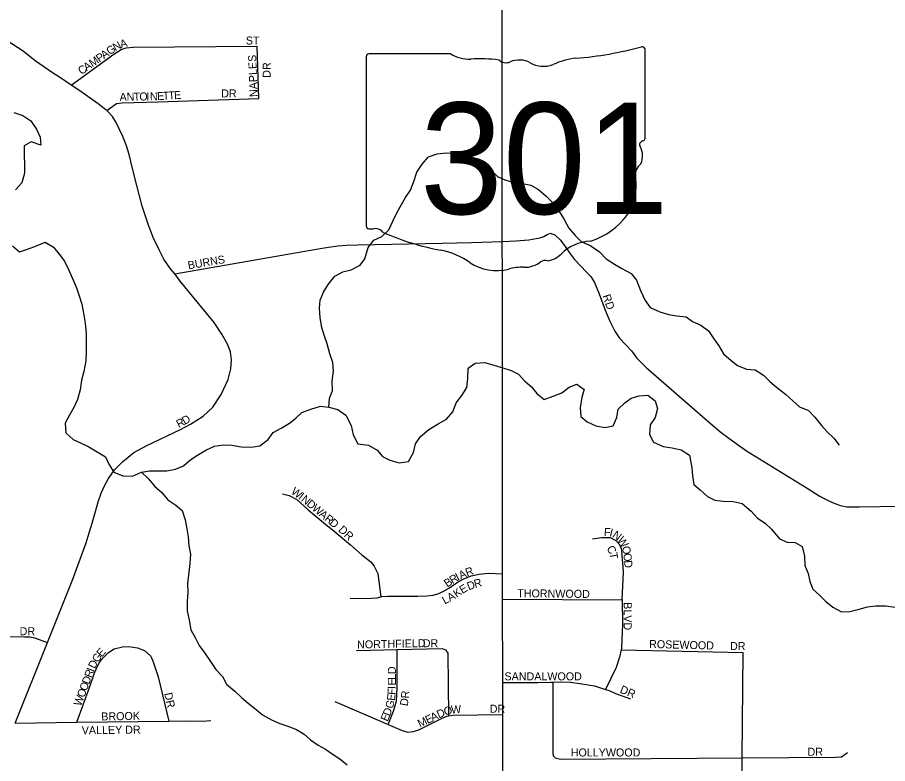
# Model space of a CAD drawing. Extents: x 1857828 to 2277390, y 930619 to 1324581.
# Drawn here: x 2081484 to 2086916, y 1239081 to 1243739 of the extents above; entities that cross this region are included whole.
import ezdxf

# ---------------------------------------------------------------- set-up
doc = ezdxf.new("R2010")
doc.units = 0
for name, color, linetype in [('GM_X_City_Street', 7, 'Continuous'), ('GM_X_City_Street_Text', 7, 'Continuous'), ('GM_X_Minor_River', 7, 'Continuous'), ('GM_X_State_Location', 7, 'Continuous'), ('GM_X_State_Route', 7, 'Continuous'), ('GM_X_State_Shield', 7, 'Continuous')]:
    doc.layers.add(name, color=color, linetype=linetype)

msp = doc.modelspace()

# ---------------------------------------------------------------- linework, layer by layer
at = {"layer": 'GM_X_City_Street'}
for points in [[(2081470.6, 1239334.1), (2081671.9, 1239837.7), (2081829.2, 1240231.2), (2081884.8, 1240380.1), (2081912.6, 1240458.5), (2081932.4, 1240520.8), (2081950.2, 1240581.1), (2081972, 1240655.5), (2081987.7, 1240713.8), (2082005.6, 1240768.1), (2082027.5, 1240814.4), (2082051.4, 1240860.7), (2082089.3, 1240915), (2082139.3, 1240965.5), (2082211.4, 1241022), (2082291.6, 1241066.6), (2082502.1, 1241166), (2082564.2, 1241200.4), (2082642.4, 1241248.9), (2082704.4, 1241305.4), (2082756.3, 1241384), (2082800.1, 1241478.6), (2082815.8, 1241544.9), (2082819.6, 1241601.1), (2082813.4, 1241651.3), (2082795, 1241699.4), (2082760.6, 1241761.4), (2082712, 1241833.4), (2082606.9, 1241963.5), (2082499.8, 1242091.4), (2082467.5, 1242137.4), (2082439.2, 1242169.4), (2082398.7, 1242229.5), (2082368.3, 1242287.5), (2082331.8, 1242365.7), (2082299.3, 1242447.8), (2082262.6, 1242560.1), (2082229.8, 1242690.4), (2082201.2, 1242794.7), (2082180.7, 1242882.9), (2082164.4, 1242937), (2082142, 1242995.2), (2082119.7, 1243043.2), (2082099.4, 1243083.3), (2082077.1, 1243119.3), (2082041.2, 1243156.6), (2082036.7, 1243161.3), (2081988.4, 1243199.2), (2081873.4, 1243280.9), (2081819.5, 1243316.5), (2081752.5, 1243360.7), (2081702.1, 1243392.6), (2081595.2, 1243468.3), (2081518.6, 1243528.2), (2081413.8, 1243596)], [(2081819.5, 1243316.5), (2082085.3, 1243508.2), (2082109.4, 1243524.2), (2082131.5, 1243538.2), (2082163.6, 1243548.2), (2082205.8, 1243552.2), (2082980.5, 1243559.4)], [(2082990.2, 1243232.6), (2082980.5, 1243559.4)], [(2082041.2, 1243156.6), (2082103, 1243201.5), (2082137.1, 1243205.4), (2082362, 1243211.2), (2082990.2, 1243232.6)], [(2084511, 1242340.9), (2084594.6, 1242344.3), (2084676.9, 1242350.7), (2084745.2, 1242363.1), (2084769.3, 1242371.3), (2084791.3, 1242383.4), (2084811.3, 1242391.5), (2084820.2, 1242388.4)], [(2084820.2, 1242388.4), (2084820.7, 1242388.2), (2084839.5, 1242381.6), (2084871.8, 1242349.7), (2084900.1, 1242315.7), (2084930.5, 1242269.7), (2084960.8, 1242227.6), (2085003.2, 1242183.7), (2085033.5, 1242151.7), (2085063.8, 1242121.7), (2085086.1, 1242083.7), (2085116.5, 1242013.6), (2085153.2, 1241911.4), (2085181.6, 1241843.2), (2085214, 1241781.1), (2085242.4, 1241737.1), (2085282.8, 1241695.1), (2085317.1, 1241657.2), (2085351.5, 1241611.2), (2085414, 1241549.2), (2085422, 1241542.3), (2085423.5, 1241541.1)], [(2082467.5, 1242137.4), (2083312.8, 1242286), (2083399.1, 1242300.5), (2083441.3, 1242306.7), (2083483.5, 1242312.9), (2083535.7, 1242317.2), (2083610, 1242319.6), (2084136.4, 1242330.1), (2084319.3, 1242333), (2084511, 1242340.9)], [(2085423.5, 1241541.1), (2085809.5, 1241205.8), (2085878.1, 1241147.9), (2085916.4, 1241118), (2085970.8, 1241078.1), (2086035.3, 1241034.2), (2086414.2, 1240799.1), (2086488.7, 1240753.3), (2086517, 1240737.4), (2086553.2, 1240719.5), (2086587.4, 1240703.6), (2086621.6, 1240691.7), (2086661.9, 1240683.9), (2086738.2, 1240684.3), (2086996.2, 1240686.9)], [(2083139.7, 1240764.4), (2083180, 1240755), (2083228.5, 1240729.6), (2083299.7, 1240664.5), (2083397.2, 1240583.7), (2083462.2, 1240532.5), (2083563.9, 1240445.7), (2083635, 1240384.6), (2083689.9, 1240339.3), (2083710.4, 1240313.6), (2083733.1, 1240267.8), (2083753.2, 1240122.1)], [(2085259.1, 1240103.2), (2085266.6, 1240275.7), (2085263.7, 1240335.8), (2085259.1, 1240375.9), (2085256.5, 1240415.9), (2085244, 1240445.8), (2085221.6, 1240471.6), (2085187.1, 1240491.1), (2085132.9, 1240490.3), (2085074.9, 1240481.5)], [(2083560.7, 1240112.9), (2083659.1, 1240112.3), (2083729.3, 1240115.3), (2083753.2, 1240122.1), (2083759.3, 1240123.8), (2083793.4, 1240126.3), (2083984.1, 1240125), (2084040.3, 1240127.8), (2084080.3, 1240132.4), (2084114.3, 1240142.9), (2084148.2, 1240159.5), (2084182.1, 1240178), (2084231.7, 1240212.8), (2084267.6, 1240231.3), (2084317.5, 1240252.1), (2084367.5, 1240262.8), (2084423.6, 1240269.7), (2084512.7, 1240264.8)], [(2084512.8, 1240106.5), (2085259.1, 1240103.2), (2085261.4, 1239946.9), (2085256.6, 1239858.6), (2085255.5, 1239800.4), (2085253.2, 1239791.1), (2085242.3, 1239746.1), (2085221.1, 1239679.7), (2085155.9, 1239543.4)], [(2080187.9, 1239829.9), (2081047.7, 1239830.3), (2081089.8, 1239832.9), (2081113.8, 1239835.2), (2081145.8, 1239843.7), (2081182.9, 1239855.4), (2081209.8, 1239864.7), (2081231.8, 1239871), (2081267.9, 1239873.5), (2081332.1, 1239874.5), (2081530.8, 1239871.3), (2081563, 1239871.8), (2081591.1, 1239866.2), (2081671.9, 1239837.7)], [(2081853.8, 1239338.6), (2081932.9, 1239556.3), (2081963.8, 1239641), (2081981.2, 1239685.3), (2081996.9, 1239711.6), (2082012.6, 1239733.9), (2082052.2, 1239774.6), (2082088, 1239797.1), (2082140, 1239809.9), (2082180.1, 1239812.4), (2082234.4, 1239803.2), (2082276.8, 1239787.8), (2082317.5, 1239752.3), (2082332.1, 1239716.4), (2082361.6, 1239622.6), (2082429.9, 1239345.3)], [(2083599.7, 1239786.7), (2083854.5, 1239792.3), (2084135.4, 1239798.4), (2084155.6, 1239790.7), (2084170, 1239770.8), (2084174.3, 1239378.9)], [(2083798, 1239325.9), (2083832.1, 1239407.1), (2083839.7, 1239435.3), (2083851.1, 1239473.6), (2083854, 1239553.8), (2083854.5, 1239792.3)], [(2085253.2, 1239791.1), (2086014.6, 1239775.3)], [(2086020.9, 1236475.6), (2086016, 1236628.4), (2086013.5, 1236704), (2086013.7, 1236969.4), (2086013.9, 1237280.7), (2086014, 1237359.6), (2086012.5, 1237660.7), (2086008.5, 1238482.2), (2086007, 1238790.9), (2086009.5, 1239117.7), (2086014.6, 1239775.3)], [(2084513.3, 1239587.2), (2084732.7, 1239586.5), (2084813, 1239589.6), (2084827, 1239589.8), (2084875.2, 1239590.5), (2084935.4, 1239589.4), (2084995.8, 1239580.2), (2085086.3, 1239565.5), (2085155.9, 1239543.4), (2085177.1, 1239536.7), (2085217.5, 1239519.2), (2085312.3, 1239484.5)], [(2084827, 1239589.8), (2084825.6, 1239142.7), (2084829.8, 1239126.8), (2084842, 1239116.9), (2084874.2, 1239109.4), (2086009.5, 1239117.7), (2086590.3, 1239122), (2086628.4, 1239122.5), (2086666.1, 1239149.1)], [(2083465.8, 1239468.1), (2083778.9, 1239334.2), (2083798, 1239325.9), (2083886, 1239287.6), (2083920.3, 1239276.1), (2083956.4, 1239280.6), (2083994.3, 1239293.2), (2084135.8, 1239365.4), (2084165.7, 1239377.9), (2084174.3, 1239378.9), (2084201.8, 1239382.4), (2084513.4, 1239386.8)], [(2081470.6, 1239334.1), (2081853.8, 1239338.6), (2082429.9, 1239345.3), (2082564.3, 1239346.9), (2082640.6, 1239345.9), (2082690.7, 1239350.7)]]:
    msp.add_lwpolyline(points, dxfattribs=at)
at = {"layer": 'GM_X_Minor_River'}
for points in [[(2081462.4, 1243144.9), (2081516.8, 1243127.4), (2081567.5, 1243093.8), (2081602.3, 1243042), (2081624.9, 1242992), (2081629.6, 1242941.8), (2081569.1, 1242961.2), (2081525.2, 1242936.6), (2081525.9, 1242878.3), (2081528.6, 1242816), (2081527.2, 1242765.8), (2081511.9, 1242705.3), (2081472.2, 1242662.6)], [(2083427.4, 1241305.6), (2083432.7, 1241360), (2083450.2, 1241410.4), (2083449.5, 1241468.7), (2083456.8, 1241531.1), (2083452.1, 1241585.3), (2083433.4, 1241639.3), (2083418.6, 1241701.5), (2083401.9, 1241749.5), (2083385.2, 1241803.6), (2083374.4, 1241863.8), (2083369.7, 1241924.1), (2083373.1, 1241974.3), (2083394.6, 1242022.8), (2083424.2, 1242071.4), (2083465.7, 1242124.1), (2083515.6, 1242150.8), (2083567.7, 1242163.4), (2083623.6, 1242192.2), (2083653.3, 1242232.7), (2083674.5, 1242303.3), (2083708.2, 1242347.9), (2083758.1, 1242370.6), (2083801.8, 1242413.3), (2083827.3, 1242467.8), (2083854.7, 1242522.4), (2083882.3, 1242570.9), (2083905.8, 1242615.4), (2083937.5, 1242660), (2083958.9, 1242714.5), (2083978.3, 1242773), (2084009.8, 1242823.6), (2084049.5, 1242868.3), (2084103.5, 1242887), (2084159.7, 1242893.6), (2084220, 1242888.3), (2084280.4, 1242880.9), (2084334.9, 1242861.4), (2084387.5, 1242829.8), (2084438.2, 1242790.2), (2084480.9, 1242746.4), (2084527.4, 1242724.9), (2084575.8, 1242709.3), (2084636.1, 1242701.9), (2084688.5, 1242692.5), (2084737, 1242664.9), (2084785.8, 1242623.2), (2084832.5, 1242575.5), (2084863.2, 1242531.6), (2084898, 1242477.8), (2084926.8, 1242423.8), (2084965.5, 1242378), (2085004.1, 1242340.2), (2085062.7, 1242312.8), (2085117.4, 1242275.2), (2085160.1, 1242231.4), (2085210.8, 1242197.8), (2085257.3, 1242172.2), (2085315.9, 1242140.7), (2085348.6, 1242098.9), (2085373.5, 1242034.8), (2085402.4, 1241970.8), (2085435, 1241927), (2085493.6, 1241901.5), (2085550.1, 1241884.1), (2085600.4, 1241876.6), (2085658.7, 1241869.2), (2085699.3, 1241839.5), (2085749.8, 1241817.9), (2085798.4, 1241782.3), (2085831.2, 1241732.4), (2085863.8, 1241688.6), (2085892.6, 1241638.6), (2085939.3, 1241596.9), (2085979.8, 1241565.2), (2086036.4, 1241543.8), (2086088.7, 1241538.3), (2086141.3, 1241504.7), (2086181.9, 1241467), (2086222.6, 1241431.3), (2086279.3, 1241387.7), (2086324, 1241346), (2086366.7, 1241308.3), (2086423.2, 1241284.8), (2086461.9, 1241243), (2086504.7, 1241191.2), (2086539.3, 1241151.4), (2086580, 1241111.7), (2086614.7, 1241067.8)], [(2081452.3, 1242312.7), (2081497, 1242275), (2081547, 1242291.6), (2081603, 1242312.4), (2081657, 1242335.1), (2081709.6, 1242303.5), (2081744.3, 1242261.7), (2081776.9, 1242217.8), (2081801.7, 1242165.8), (2081828.5, 1242107.9), (2081853.3, 1242049.8), (2081870, 1241999.8), (2081886.7, 1241947.7), (2081895.4, 1241891.5), (2081906.2, 1241829.3), (2081913, 1241765.1), (2081913.7, 1241704.8), (2081912.4, 1241648.5), (2081911, 1241594.2), (2081897.7, 1241527.8), (2081884.3, 1241473.3), (2081875, 1241414.9), (2081859.6, 1241354.5), (2081836.1, 1241304), (2081810.6, 1241259.5), (2081781.1, 1241204.9), (2081785.8, 1241144.6), (2081832.5, 1241104.9), (2081881, 1241081.4), (2081929.5, 1241057.8), (2081982.1, 1241026.2), (2082032.7, 1240996.6), (2082055.4, 1240950.7), (2082086.1, 1240900.8), (2082142.7, 1240877.3), (2082202.9, 1240875.9), (2082258.9, 1240900.7), (2082309, 1240909.3), (2082363.3, 1240907.9), (2082417.5, 1240908.5), (2082471.7, 1240919.1), (2082521.6, 1240939.8), (2082567.4, 1240978.5), (2082615.2, 1241011.2), (2082665.1, 1241039.9), (2082715, 1241062.5), (2082769.2, 1241071.2), (2082821.5, 1241067.7), (2082879.8, 1241058.3), (2082942.1, 1241057), (2082996.3, 1241063.7), (2083050.1, 1241104.4), (2083079.7, 1241147), (2083129.6, 1241173.7), (2083181.4, 1241206.4), (2083221.3, 1241237), (2083259, 1241271.6), (2083315, 1241294.3), (2083375.1, 1241311.1), (2083427.4, 1241305.6), (2083483.8, 1241290.2), (2083534.4, 1241256.6), (2083567.4, 1241190.6), (2083580.1, 1241132.5), (2083608.9, 1241076.5), (2083675.3, 1241069.2), (2083730, 1241037.7), (2083762.6, 1240997.8), (2083809.1, 1240974.2), (2083867.5, 1240958.8), (2083925.7, 1240967.5), (2083957.2, 1241022.1), (2083968.6, 1241076.5), (2084000.2, 1241123.1), (2084051.9, 1241165.9), (2084109.7, 1241202.7)], [(2084109.7, 1241202.7), (2084161.6, 1241231.4), (2084201.2, 1241276.1), (2084222.7, 1241332.6), (2084258.3, 1241379.2), (2084289.8, 1241427.8), (2084295.2, 1241484.1), (2084298.4, 1241548.5), (2084342.2, 1241581.1), (2084402.5, 1241583.8), (2084458.9, 1241568.4), (2084513.4, 1241550.9), (2084565.8, 1241535.4), (2084612.3, 1241511.8), (2084651, 1241468), (2084693.6, 1241432.3), (2084726.2, 1241390.5), (2084772.9, 1241352.8), (2084828.9, 1241373.5), (2084882.9, 1241396.2), (2084928.7, 1241430.9), (2084976.7, 1241449.5), (2085021.3, 1241415.9), (2085007.8, 1241367.5), (2084996.6, 1241301), (2085001.2, 1241246.8), (2085041.8, 1241215.1), (2085094.3, 1241189.6), (2085150.7, 1241178.1), (2085202.8, 1241188.8), (2085226.3, 1241241.3), (2085233.7, 1241293.6), (2085275.4, 1241332.3), (2085315.3, 1241362.9), (2085365.3, 1241375.5), (2085419.5, 1241380.1), (2085466.2, 1241344.4), (2085480.8, 1241296.4), (2085465.4, 1241241.9), (2085433.8, 1241195.4), (2085430.5, 1241135), (2085455.2, 1241087.1), (2085515.8, 1241059.6), (2085572.1, 1241052.2), (2085628.6, 1241038.7), (2085679.2, 1241005.1), (2085694.2, 1240926.9), (2085698.8, 1240876.7), (2085707.5, 1240822.6), (2085746.1, 1240788.8), (2085792.8, 1240749.1), (2085837.3, 1240725.5), (2085889.6, 1240718.1), (2085951.9, 1240716.7), (2086008.3, 1240705.3), (2086065.1, 1240655.7), (2086103.8, 1240613.9), (2086152.4, 1240582.3), (2086191, 1240544.5), (2086242, 1240484.8), (2086288.4, 1240463.2), (2086338.7, 1240461.8), (2086383.2, 1240436.1), (2086398, 1240376), (2086400.7, 1240317.8), (2086421.4, 1240267.7), (2086430, 1240217.6), (2086450.7, 1240169.6), (2086491.3, 1240131.8), (2086530, 1240092.1), (2086574.6, 1240056.4), (2086629.2, 1240028.9), (2086681.4, 1240029.4), (2086739.5, 1240044.1), (2086791.6, 1240058.8), (2086843.7, 1240065.4), (2086904, 1240066.1), (2086964.4, 1240056.7)], [(2082258.9, 1240900.7), (2082301.6, 1240858.9), (2082342.4, 1240811.1), (2082383, 1240775.4), (2082423.7, 1240727.6), (2082472.4, 1240694), (2082512.9, 1240660.3), (2082531.7, 1240602.2), (2082542.4, 1240546.1), (2082549.1, 1240495.9), (2082553.8, 1240439.7), (2082564.4, 1240387.5), (2082561.1, 1240329.2), (2082552, 1240256.7), (2082544.6, 1240204.4), (2082547.2, 1240148.1), (2082543.9, 1240093.8), (2082542.6, 1240033.5), (2082555.3, 1239975.4), (2082566.1, 1239915.2), (2082594.9, 1239863.3), (2082617.5, 1239817.3), (2082654.3, 1239769.5), (2082689, 1239717.6), (2082721.8, 1239667.7), (2082764.5, 1239624), (2082789.2, 1239576), (2082842, 1239532.4), (2082882.6, 1239492.6), (2082925.2, 1239458.9), (2082973.9, 1239419.3), (2083014.5, 1239385.6), (2083069.1, 1239354), (2083121.6, 1239330.5), (2083172.1, 1239315), (2083226.6, 1239293.5), (2083273.1, 1239263.8), (2083313.7, 1239230.1), (2083362.3, 1239196.5), (2083406.9, 1239170.9), (2083449.4, 1239141.2), (2083496, 1239109.6), (2083542.6, 1239073.9)]]:
    msp.add_lwpolyline(points, dxfattribs=at)
at = {"layer": 'GM_X_State_Route'}
for points in [[(2084511.2, 1242128.7), (2084511, 1242340.9), (2084510.6, 1245149.1), (2084510.6, 1245149.6)], [(2084489, 1233755.1), (2084490.4, 1234000.5), (2084492.1, 1234314.5), (2084495.6, 1234939.9), (2084498.2, 1235411.2), (2084503.3, 1236323.2), (2084505.4, 1236702.2), (2084507.3, 1237059), (2084510.6, 1237636.6), (2084512.3, 1237949.2), (2084514.3, 1238308.8), (2084513.8, 1238925.5), (2084513.4, 1239386.8), (2084513.3, 1239587.2), (2084512.8, 1240106.5), (2084512.7, 1240264.8), (2084511.2, 1242128.7), (2084511.2, 1242128.7)]]:
    msp.add_lwpolyline(points, dxfattribs=at)
at = {"layer": 'GM_X_State_Shield'}
for p, q in [((2084188.7, 1243511.7), (2083679.1, 1243511.7)), ((2085402.1, 1242985.1), (2085402.1, 1243537.9)), ((2083661.9, 1243493.5), (2083661.9, 1242436.9)), ((2085402, 1242985.3), (2085402.1, 1242985.1))]:
    msp.add_line(p, q, dxfattribs=at)
for centre, major_axis, start_param, end_param in [((2083681.9, 1243495.8), (20.2, 0), 1.712693, 3.28349), ((2084310.1, 1243634.4), (195.5, 0), 4.042523, 4.731795), ((2084782.3, 1244952.2), (1845.5, 0), 4.814394, 5.042369), ((2085382.8, 1243540.2), (19.4, 0), 6.141152, 7.989035), ((2084374.9, 1242918.5), (702, 0), 1.404758, 1.657858), ((2084534.3, 1243501.2), (56.4, 0), 3.836095, 5.185415), ((2084617.1, 1243379.1), (117.3, 0), 0.950623, 2.079405), ((2084768.5, 1243546.6), (141.1, 0), 4.081561, 5.145723), ((2085017.7, 1243189), (371.3, 0), 1.699011, 2.107814), ((2085397.7, 1242944.6), (30, 0), 1.883978, 3.671073), ((2085381.5, 1242983), (20.7, 0), 5.05454, 6.418171), ((2085206.9, 1242874.7), (180, 0), 5.934695, 6.695948), ((2085471.6, 1242753.8), (130.9, 0), 2.387724, 3.262537), ((2084885.6, 1242683.5), (461.6, 0), 5.101752, 6.440018), ((2083682.1, 1242434.6), (20.3, 0), 3.00124, 4.508301), ((2083685.1, 1242542.7), (155.2, 0), 4.665946, 4.897461), ((2083716.9, 1242375.9), (56, 0), 0.519207, 1.627899), ((2084423.5, 1243325.3), (1332.7, 0), 4.195997, 4.488961), ((2085080.3, 1242140.2), (252.8, 0), 1.647645, 2.488434), ((2084026.2, 1241962.2), (417, 0), 0.823519, 1.323587), ((2084760, 1242334.5), (149.1, 0), 4.937069, 5.64225), ((2084477.2, 1242370.7), (264.6, 0), 4.026481, 4.996735), ((2084649.4, 1242291.5), (141, 0), 4.691044, 5.507374), ((2084776.9, 1242189.2), (39.7, 0), 1.147584, 2.315152), ((2084630, 1242005.4), (217.4, 0), 1.495662, 1.94098)]:
    msp.add_ellipse(centre, major_axis=major_axis, ratio=0.8, start_param=start_param, end_param=end_param, dxfattribs=at)

# ---------------------------------------------------------------- texts
at = {"layer": 'GM_X_City_Street_Text'}
for s, rotation, p in [('ST', 0, (2082909.9, 1243569.3)), ('G', 34.9508, (2082060.4, 1243501.9)), ('N', 28.3348, (2082095.2, 1243526.3)), ('A', 15.7593, (2082131.2, 1243546.1)), ('P', 34.943, (2081995.5, 1243456.5)), ('A', 34.9508, (2082024.3, 1243476.7)), ('A', 34.9508, (2081916.1, 1243401.1)), ('M', 34.9532, (2081952.2, 1243426.3)), ('NAPLES', 92.2016, (2082984.1, 1243242.7)), ('DR', 90, (2083064.8, 1243361.9)), ('C', 34.9562, (2081883.7, 1243378.4)), ('A', 1.0929, (2082122.1, 1243217.3)), ('N', 1.0492, (2082166.1, 1243218.1)), ('T', 1.0746, (2082210.1, 1243218.9)), ('O', 1.0929, (2082245.3, 1243219.6)), ('I', 1.0488, (2082289.3, 1243220.5)), ('N', 1.2994, (2082311.5, 1243220.9)), ('E', 2.7665, (2082356.9, 1243221.9)), ('T', 3.3798, (2082392.7, 1243223.6)), ('T', 3.3889, (2082427.8, 1243225.7)), ('E', 3.3344, (2082463, 1243227.8)), ('DR', 0, (2082755.9, 1243239.3)), ('BURNS', 9.861, (2082551.9, 1242165.6)), ('RD', 288.4386, (2085136.4, 1242000.9)), ('R', 28.5097, (2082492, 1241174.7)), ('D', 30.5441, (2082528.4, 1241194.5)), ('W', 324.2767, (2083187.9, 1240769.3)), ('I', 321.6268, (2083233.9, 1240736.3)), ('N', 320.4938, (2083250.9, 1240722.8)), ('D', 320.4184, (2083284.9, 1240694.8)), ('W', 320.4054, (2083318.8, 1240666.7)), ('A', 320.3847, (2083362.9, 1240630.3)), ('R', 320.4147, (2083396.8, 1240602.2)), ('D', 320.4184, (2083427.3, 1240577)), ('DR', 317.1199, (2083483.9, 1240535.2)), ('F', 357.1581, (2085144.4, 1240502.5)), ('I', 346.2288, (2085177.1, 1240501.1)), ('N', 323.5193, (2085193.7, 1240498.1)), ('W', 305.2758, (2085226.2, 1240475)), ('C', 301.3053, (2085159.9, 1240423.6)), ('O', 282.2657, (2085257.1, 1240433.1)), ('T', 279.2198, (2085178.7, 1240394.5)), ('O', 276.0674, (2085266.2, 1240391.5)), ('R', 20.539, (2084291.3, 1240248.1)), ('D', 275.4497, (2085270.8, 1240347.9)), ('R', 32.1676, (2084200.2, 1240200.7)), ('I', 25.9784, (2084232.4, 1240221.1)), ('A', 23.9936, (2084251.8, 1240230.5)), ('B', 33.6227, (2084167.5, 1240179)), ('E', 31.0669, (2084261.4, 1240139.4)), ('D', 20.8272, (2084301.5, 1240162)), ('R', 15.0847, (2084341.3, 1240177.2)), ('A', 30.0107, (2084184.1, 1240091)), ('K', 34.1674, (2084225.6, 1240115.1)), ('THORNWOOD', 359.3707, (2084604, 1240119.7)), ('L', 28.1046, (2084151.5, 1240073.5)), ('BLVD', 270, (2085268.9, 1240088.3)), ('DR', 0, (2081497.5, 1239882.1)), ('NORTHFIELD', 1.3174, (2083605, 1239798.5)), ('DR', 0, (2084014.3, 1239807.3)), ('ROSEWOOD', 358.5506, (2085426.9, 1239802.9)), ('DR', 0, (2085932.7, 1239789.7)), ('G', 55.1942, (2081985.7, 1239707.2)), ('E', 48.9066, (2082010, 1239742.2)), ('D', 63.826, (2081967.3, 1239669.4)), ('R', 69.5314, (2081946.3, 1239612.9)), ('I', 69.5389, (2081960.2, 1239650)), ('D', 90.0038, (2083846.5, 1239639.5)), ('SANDALWOOD', 0, (2084524.7, 1239600.5)), ('D', 69.535, (2081930.9, 1239571.7)), ('E', 89.7441, (2083846.3, 1239568.8)), ('L', 89.9821, (2083846.5, 1239604.3)), ('O', 69.535, (2081900.2, 1239489.3)), ('O', 69.535, (2081915.5, 1239530.5)), ('F', 87.112, (2083843.8, 1239509.2)), ('I', 88.2322, (2083845.6, 1239545.4)), ('DR', 337.6115, (2085241, 1239525)), ('W', 69.5227, (2081880.1, 1239435.7)), ('DR', 282.5301, (2082399.8, 1239518.3)), ('E', 83.8294, (2083839.8, 1239471)), ('D', 79.6971, (2083919.3, 1239437)), ('R', 86.108, (2083927.9, 1239486.3)), ('G', 75.5247, (2083827.4, 1239420.7)), ('O', 16.2637, (2084153.5, 1239380.3)), ('W', 4.9493, (2084193.1, 1239392.1)), ('DR', 0, (2084432.3, 1239398.1)), ('BROOK', 1.1685, (2082007.7, 1239349.7)), ('E', 67.0059, (2083794.5, 1239339.8)), ('D', 67.9827, (2083808.6, 1239373.1)), ('E', 25.7068, (2084044.5, 1239327.6)), ('A', 25.6851, (2084076.2, 1239342.9)), ('D', 25.714, (2084115.9, 1239362)), ('M', 25.6935, (2083996.9, 1239304.7)), ('VALLEY DR', 0.7341, (2081885.7, 1239263.7)), ('HOLLYWOOD', 0, (2084938.3, 1239125.3)), ('DR', 0, (2086416.7, 1239129.7))]:
    msp.add_text(s, height=50, rotation=rotation, dxfattribs=at).set_placement(p)
at = {"layer": 'GM_X_State_Location'}
for s in ['s', 'r']:
    msp.add_text(s, height=1, dxfattribs=at).set_placement((2084512.5, 1242894.9))
msp.add_text('301', height=1, rotation=0, dxfattribs=at).set_placement((2084159.5, 1242822.2))
at = {"layer": 'GM_X_State_Shield'}
msp.add_text('301', height=696.1, dxfattribs=at).set_placement((2083996.6, 1242511.4))

doc.saveas('drawing.dxf')
